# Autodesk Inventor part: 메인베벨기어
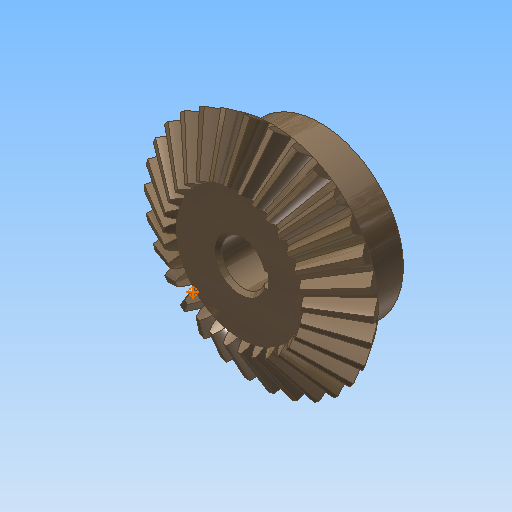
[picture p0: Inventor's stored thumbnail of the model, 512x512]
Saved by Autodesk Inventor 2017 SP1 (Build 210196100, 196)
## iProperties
Created: 2018-09
Part Number: 메인베벨기어
Material: 강철, 탄소
Document SubType Name: Modeling
Categories: <?xml version="1.0" encoding="UTF-16"?> <MemberInstance><Categories><FamilyTemplate><FamilyTemplateParameter ValueType="xs:double" Id="1" ObjectReferenceKey="da
Mass: 290.333 g
Surface Area: 107.709 cm^2
Volume: 36.8911 cm^3
Density: 7.87 g/cm^3
Appearance: 얼룩무늬
CustomPartVersion: 1
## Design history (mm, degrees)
node "맨 위 점"
node "메쉬 평면2"
sketch "톱니 본체 스케치"
  geometry: L1 (0, 0)-(28.669, -21.997); L2 (28.669, -21.997)-(31.109, -18.336); L3 (31.109, -18.336)-(0, 0); L4 (30, -20)-(0, 0); L5 (17.219, -13.212)-(18.685, -11.013); L6 (28.669, -21.997)-(17.219, -13.212); L7 (31.109, -18.336)-(18.685, -11.013); L8 (0, -39.387)-(0, 6.564) reference; L9 (0, -20)-(31.109, -20)
  constraints: 16 end point, 4 point on line, 3 perpendicular, 2 collinear, 1 horizontal alignment, 1 vertical alignment
  dimensions: "d0" = 60 diameter of L4.start L8 (= da_de); "d1" = 57.33744 diameter of L1.end L8 (= da_dfe); "d2" = 62.2188 diameter of L2.end L8 (= da_dae); "d3" = 14.4 distance between parallel lines of L2 L5 (= da_b); "d4" = 18.3359 vertical distance of L2.end L1.start (= da_ve)
revolve "톱니 본체" sketch "톱니 본체 스케치" stored, may be unused: angle "d5" = 90 deg
node "시작점"
node "톱니 평면"
sketch "시작 스케치"
  geometry: L1 (0, -23.505)-(0, 10.645) reference; L2 (-0.709, -2.928)-(0.709, -2.928); A1 r 19.188 centre (-19.457, -7.014) between (-0.709, -2.928) and (-3.232, 3.229); A2 r 19.188 centre (19.457, -7.014) between (3.232, 3.229) and (0.709, -2.928); A3 r 57.403 centre (0, -54.083) between (3.232, 3.229) and (-3.232, 3.229); 1 further point
  constraints: 6 point on circle, 3 centre point, 3 symmetric about line, 2 end point, 1 coincident, 1 perpendicular, 1 other
  dimensions: "d7" = 19.18795 radius of A1 (= fd_rr); "d8" = 19.45712 horizontal distance of point (0, -54.083) A1.centre (= fd_x); "d9" = 47.06905 vertical distance of point (0, -54.083) A1.centre (= fd_y); "d57" = 57.40327 radius of A3 (= 0.5 x fd_dva + 0.3 x da_he); "d58" = 51.15527 distance from line of A3.centre L2 (= 0.5 x fd_dva - 1.12 x da_he)
node "끝점"
  node "끝 평면"
sketch "3D 스케치 오른쪽"
  node "Helical Curve Right" dims "d65" = 229.90621 (computed from da_dm, da_delta, da_beta), "d66" = 31.5, "d67" = 60 (= da_de), "d68" = -9.82794 (= -da_delta), "d69" = 8.10972 (computed from fd_loft, da_delta)
node "끝 평면 오른쪽"
sketch "끝 스케치 오른쪽"
  geometry: L1 (0, -41.54)-(0, 13.178) reference; L2 (-0.422, -1.69)-(0.422, -1.69); A1 r 11.427 centre (-11.587, -4.123) between (-0.422, -1.69) and (-1.925, 1.977); A2 r 11.427 centre (11.587, -4.123) between (1.925, 1.977) and (0.422, -1.69); A3 r 34.184 centre (0, -32.153) between (1.925, 1.977) and (-1.925, 1.977); 1 further point
  constraints: 6 point on circle, 3 centre point, 3 symmetric about line, 2 end point, 1 coincident, 1 perpendicular, 1 other
  dimensions: "d70" = 11.58699 horizontal distance of A3.centre A1.centre (computed from fd_x, fd_ratio); "d71" = 28.03028 vertical distance of point (0, -32.153) A1.centre (computed from fd_y, fd_ratio); "d72" = 11.4267 radius of A1 (computed from fd_rr, fd_ratio); "d73" = 30.46369 distance from line of point (0, -32.153) L2 (computed from d58, fd_ratio); "d74" = 34.18446 radius of A3 (computed from d57, fd_ratio)
feature "로프트 오른쪽" sketch "끝 스케치 오른쪽" dims "d75" = 0, "d77" = 0, "d79" = 0, "d80" = 90 deg, "d85" = 20, "d92" = 90 deg, "d93" = 90 deg, "da_teethtype" = 0 [user parameter]
sketch "3D 스케치 왼쪽"
  node "Helical Curve Left" dims "d26" = 229.90621 (computed from da_dm, da_delta, da_beta), "d27" = 8.10972 (computed from fd_loft, da_delta), "d28" = 60 (= da_de), "d29" = -9.82794 (= -da_delta)
node "끝 평면 왼쪽"
sketch "끝 스케치 왼쪽" dims "d56" = 10.3728 (derived)
  geometry: L1 (0, -43.753)-(0, 15.405) reference; L2 (-0.422, -1.678)-(0.422, -1.678); A1 r 11.427 centre (-11.587, -4.111) between (-0.422, -1.678) and (-1.925, 1.988); A2 r 11.427 centre (11.587, -4.111) between (1.925, 1.988) and (0.422, -1.678); A3 r 34.184 centre (0, -32.142) between (1.925, 1.988) and (-1.925, 1.988); 2 further points; 1 other entity
  constraints: 6 point on circle, 3 centre point, 3 symmetric about line, 2 end point, 1 coincident, 2 other
  dimensions: "d30" = 11.4267 radius of A1 (computed from fd_rr, fd_ratio); "d31" = 11.58699 horizontal distance of point (0, -32.142) A1.centre (computed from fd_x, fd_ratio); "d32" = 28.03028 vertical distance of A1.centre point (0, -32.142) (computed from fd_y, fd_ratio); "d61" = 34.18446 radius of A3 (computed from d57, fd_ratio); "d62" = 30.46369 distance from line of point (0, -32.142) L2 (computed from d58, fd_ratio)
feature "로프트 왼쪽" sketch "끝 스케치 왼쪽" dims "d35" = 0, "d37" = 0, "d39" = 0, "d40" = 90 deg, "d84" = 10, "d90" = 90 deg, "d91" = 90 deg, "da_teethtype" = 0 [user parameter]
sketch "본체 스케치"
  geometry: L1 (0, -35.038)-(0, -19.531) reference; L2 (28.669, -21.997)-(17.219, -13.212) reference; L3 (17.219, -13.212)-(0, -13.212); L4 (28.669, -21.997)-(0, -21.997)
  constraints: 4 end point, 2 perpendicular, 2 point on line
revolve "본체 고정" sketch "본체 스케치" stored, may be unused: angle "d46" = 90 deg
feature "피치 지름" dims angle "d47" = 90 deg
sketch "스케치8"
  geometry: C1 r 22.5 at (0, 0); 1 further point
  constraints: 1 centre point, 1 coincident
  dimensions: "d94" = 45 diameter of C1
extrude "돌출1" join sketch "스케치8" distance "d95" = 13; taper "d96" = 0 deg
sketch "스케치9"
  geometry: 1 further point
hole "구멍1" sketch "스케치9" at (0, 0) diameter "d97" = 12; stored, may be unused: countersink angle "d101" = 90 deg, drill point angle "d103" = 118 deg; dims "d98" = 6, "d99" = 4, "d100" = 2, "d102" = 8
sketch "스케치10"
  geometry: L1 (5.657, 2)-(7.8, 2); L2 (7.8, 2)-(7.8, -2); L3 (7.8, -2)-(5.657, -2); A1 r 6 centre (0, 0) between (5.657, 2) and (5.657, -2) reference; 1 further point
  constraints: 6 end point, 2 parallel, 2 point on circle, 1 horizontal, 1 perpendicular
  dimensions: "d104" = 4 distance of L1.end L2.end; "d112" = 13.8 dimension on A1 L2
extrude "돌출2" cut sketch "스케치10" stored distance "d106" = 10; taper "d107" = 0 deg
chamfer "모따기1" distance "d108" = 1; stored, may be unused: second distance "d109" = 2, angle "d110" = 45 deg
fillet "모깎기1" dims "d111" = 2
body "Solid1"
feature "로프트" dims "d17" = 0, "d18" = 90 deg, "d19" = 0, "d20" = 90 deg, "d89" = 0, "da_teethtype" = 0 [user parameter]
pattern_circular "원형 패턴" dims angle "d22" = 360 deg, "d88" = 0, "da_teethtype" = 0 [user parameter]
pattern_circular "원형 패턴 오른쪽" dims angle "d82" = 360 deg, "da_teethtype" = 0 [user parameter]
pattern_circular "원형 패턴 왼쪽" dims angle "d42" = 360 deg, "da_teethtype" = 0 [user parameter]
sketch "끝 스케치"
  geometry: L1 (0, -15.359)-(0, 6.983) reference; L2 (-0.422, -1.69)-(0.422, -1.69); A1 r 11.427 centre (-11.587, -4.123) between (-0.422, -1.69) and (-1.925, 1.977); A2 r 11.427 centre (11.587, -4.123) between (1.925, 1.977) and (0.422, -1.69); A3 r 34.184 centre (0, -32.153) between (1.925, 1.977) and (-1.925, 1.977); 1 further point
  constraints: 6 point on circle, 3 centre point, 3 symmetric about line, 2 end point, 1 coincident, 1 other
  dimensions: "d12" = 11.4267 radius of A1 (computed from fd_rr, fd_ratio); "d15" = 11.58699 horizontal distance of A1.centre point (0, -32.153) (computed from fd_x, fd_ratio); "d16" = 28.03028 vertical distance of A1.centre point (0, -32.153) (computed from fd_y, fd_ratio); "d59" = 34.18446 radius of A3 (computed from d57, fd_ratio); "d60" = 30.46369 distance from line of A3.centre L2 (computed from d58, fd_ratio)
sketch "Sketch6"
  geometry: L1 (30, -20)-(0, 0) reference; L2 (0, -37.8)-(0, 6.3) reference
body "Srf1"
other parameters: "da_b" = 14.4 [user parameter; used in 2 equation terms], "da_de" = 60 [user parameter; used in 4 equation terms], "da_dae" = 62.2188 [user parameter; used in 2 equation terms], "da_dfe" = 57.33744 [user parameter; used in 1 equation term], "da_le" = 36.05551 [user parameter; used in 1 equation term], "da_omega" = 90 deg [user parameter; used in 1 equation term], "da_beta" = 0 [user parameter; used in 2 equation terms], "da_delta" = 9.82794 [user parameter; used in 8 equation terms], "da_alpha" = 20 deg [user parameter; used in 2 equation terms], "da_he" = 4.4 [user parameter; used in 4 equation terms], "da_ve" = 18.3359 [user parameter; used in 1 equation term], "fd_dv" = 108.16654 (computed from da_de, da_delta) [user parameter; used in 1 equation term], "fd_dva" = 112.16654 (computed from da_dae, da_delta) [user parameter; used in 3 equation terms], "fd_dvb" = 101.6433 (computed from fd_dv, da_alpha) [user parameter; used in 2 equation terms], "da_zv" = 540.83269 [user parameter; used in 1 equation term], "fd_loft" = 14.62 (= da_b + 0.05 x da_he) [user parameter; used in 4 equation terms], "fd_ratio" = 5.95514 (computed from da_le, fd_loft) [user parameter; used in 15 equation terms], "fd_rr" = 19.18795 (computed from fd_dd, fd_dvb) [user parameter; used in 6 equation terms], "fd_angle" = 0.29367 (computed from da_zv) [user parameter; used in 4 equation terms], "fd_x1" = 1.58802 (computed from da_dvw, fd_angle) [user parameter; used in 1 equation term], "fd_y1" = 54.05995 (computed from da_dvw, fd_angle) [user parameter; used in 1 equation term], "fd_x2" = 17.8691 (computed from fd_rr, fd_angle2, fd_angle) [user parameter; used in 1 equation term], "fd_y2" = 6.9909 (computed from fd_rr, fd_angle2, fd_angle) [user parameter; used in 1 equation term], "fd_x" = 19.45712 (= fd_x1 + fd_x2) [user parameter; used in 4 equation terms], "fd_y" = 47.06905 (= fd_y1 - fd_y2) [user parameter; used in 4 equation terms], "fd_angle2" = 3.43555 (computed from fd_dvb, fd_dd, da_alpha) [user parameter; used in 2 equation terms], "fd_dd" = 108.64654 (= fd_dva - 0.8 x da_he) [user parameter; used in 2 equation terms], "da_dvw" = 108.16654 [user parameter; used in 2 equation terms], "d11" = 14.62 (= fd_loft), "da_dm" = 48.01848 [user parameter; used in 2 equation terms], "da_x" = 0 [user parameter], "da_m" = 2 [user parameter], "d48" = 0, "d49" = 0, "d50" = 90 deg (= da_omega), "d51" = 6 deg (computed from da_z), "d52" = 0, "d53" = 0, "d54" = 0
